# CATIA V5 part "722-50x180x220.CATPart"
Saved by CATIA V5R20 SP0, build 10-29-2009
Part number: 722-50x180x220
Definition: NONE
Nomenclature: 722-50x180x220
Source: Unknown
Description: 722-50x180x220
Bounding box of the stored display mesh (mm): x -25 to 25, y -25 to 25, z -162 to 58
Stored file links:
  C:\Users\Utente\Desktop\IO LAVORO\3D X SITO CF\X SITO\722\722-50x180x220.CATPart
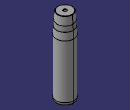
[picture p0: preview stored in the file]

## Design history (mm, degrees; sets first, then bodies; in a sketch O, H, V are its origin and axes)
Body1 "722-50x180x220" (main body)
  Solid1: solid without history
